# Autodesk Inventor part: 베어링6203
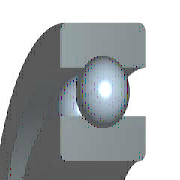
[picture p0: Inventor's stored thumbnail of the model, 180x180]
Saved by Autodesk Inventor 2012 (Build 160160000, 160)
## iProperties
IsCustomPart: 0
Company: 한국ATC센터
Created: 2014-12
Part Number: 베어링6203
Material: 강, 연강
Description: 깊은 그루브 볼 베어링
Document SubType Name: Modeling
Standard: KS B 2023
Designer: KYOUNG IL JANG
Standards Organization: KS
Language: ko-KR
Size Designation: 6203 - 17 x 40 x 12
Categories: <MemberInstance><Categories><Category DisplayName="샤프트 부품" InternalName="7f7aeb1f-a693-4053-b835-cee3144e0d98" Mnemonic="SHFT"><Category DisplayName="베어링" Inter
Density: 7.86 g/cm^3
Mass: 64.9809 g
Surface Area: 64.3582 cm^2
Volume: 8.26729 cm^3
Author: KYOUNG IL JANG
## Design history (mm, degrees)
revolve "본체" stored, may be unused: angle "d6" = 90 deg
revolve "볼" stored, may be unused: angle "d7" = 90 deg
pattern_circular "IDS_ARRAYBALL[SIMPL:T]" dims angle "d3" = 360 deg
body "Solid1"
sketch "스케치" dims "d0" = 5.98 (= -0.26 x WD + 0.26 x BD)
  geometry: L1 (3.01, 14.25)-(8.99, 14.25); L2 (6, 14.25)-(6, 11.26); L3 (6, 14.25)-(6, 17.24); L4 (3.778, 12.249)-(0, 12.249); L5 (0, 8.5)-(12, 8.5); L6 (3.778, 16.251)-(0, 16.251); L7 (0, 20)-(12, 20); L8 (12, 8.5)-(12, 12.249); L9 (8.222, 12.249)-(12, 12.249); L10 (8.222, 16.251)-(12, 16.251); L11 (12, 20)-(12, 16.251); L12 (-1.4, 0)-(8.4, 0) reference; L13 (0, -0.3)-(0, 5.3) reference
  constraints: 22 end point, 4 point on line, 2 collinear, 2 perpendicular, 2 symmetric about line, 1 midpoint, 1 parallel, 14 other
  dimensions: "d9" = 17 diameter of L5 L12 (= WD); "d11" = 40 diameter of L7 L12 (= BD); "d12" = 12 distance between parallel lines of L8 L13 (= KB); "d13" = 24.498 diameter of L9 L12 (= 0.326 x BD + 0.674 x WD)
fillet "모깎기1" dims "d1" = 0.6 (= KRS)
other parameters: "WD" = 17 [user parameter; used in 5 equation terms], "BD" = 40 [user parameter; used in 5 equation terms], "KB" = 12 [user parameter; used in 1 equation term], "KRS" = 0.6 [user parameter; used in 1 equation term], "d4" = 0, "d5" = 0, "d8" = 0, "d14" = 0, "d15" = 0, "BBA" = 0 [user parameter], "BC0" = 4750000 [user parameter], "BC" = 9560000 [user parameter], "WR" = 8.5 (= 0.5 x WD) [user parameter]
